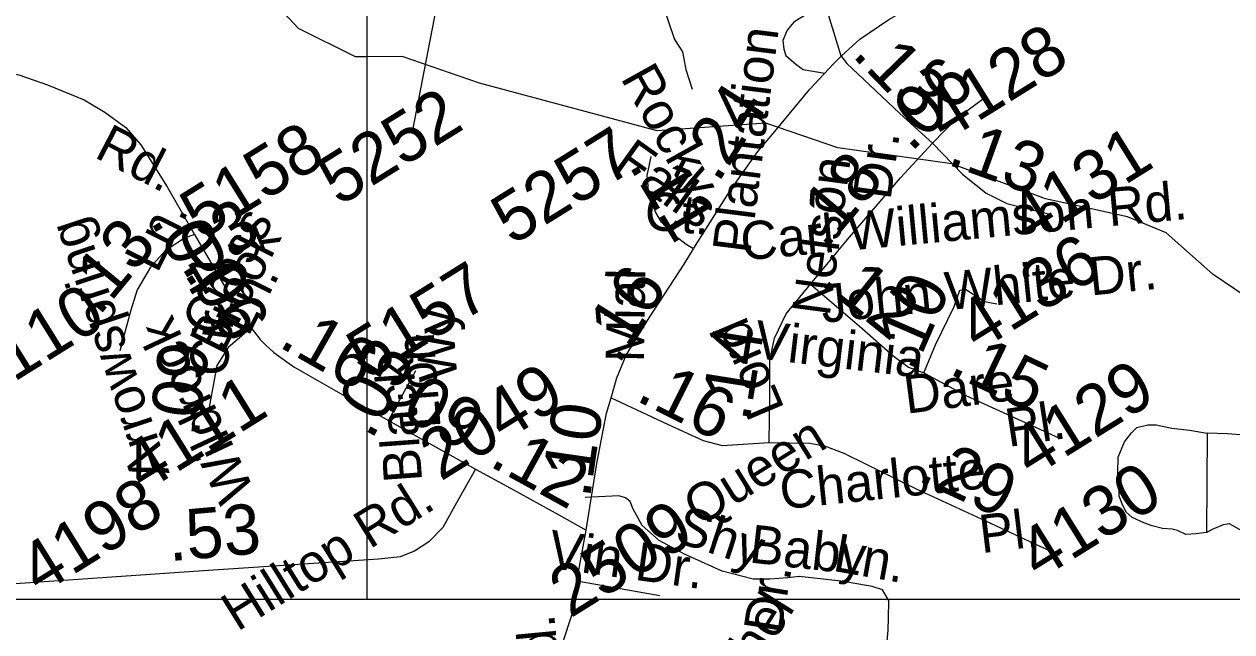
# Model space of a CAD drawing. Extents: x 2001466 to 31450019, y -30647475 to 847247.
# Drawn here: x 2156218 to 2162232, y 718722 to 721748 of the extents above; entities that cross this region are included whole.
import ezdxf

# ---------------------------------------------------------------- set-up
doc = ezdxf.new("R2010")
doc.units = 0
for name, color, linetype in [('Exist Hydrographic Misc Water Feature', 7, 'Continuous'), ('Exist Road Non-System Type 51', 7, 'Continuous'), ('Exist Road Non-System Type 51 Label', 7, 'Continuous'), ('Exist Road Secondary Mileage Hundredths English Label', 7, 'Continuous'), ('Exist Road Secondary Type 51 Attributed', 7, 'Continuous'), ('Exist Road Secondary Type 51 Label', 7, 'Continuous'), ('Exist Road Secondary Type 51 Number Label', 7, 'Continuous'), ('Map Preparation Inset Cut Line', 7, 'Continuous')]:
    doc.layers.add(name, color=color, linetype=linetype)

msp = doc.modelspace()

# ---------------------------------------------------------------- linework, layer by layer
at = {"layer": 'Exist Hydrographic Misc Water Feature'}
for points in [[(2157924.3, 721585.8), (2157868.1, 721585.3), (2157584.1, 721725.6), (2157215.2, 722123.5), (2157073.1, 722172.4), (2156940.2, 722188.2)], [(2161525.2, 720829.9), (2161304.1, 720878.7), (2160837, 721052.3), (2160270, 721132.8), (2159911, 721254.9), (2159370.1, 721216.8), (2158485.1, 721454.6), (2158101, 721587.1), (2157924.3, 721585.8)], [(2162725.1, 720105), (2162139.1, 720500.8), (2161905.1, 720709), (2161713, 720788.4), (2161525.2, 720829.9)]]:
    msp.add_lwpolyline(points, dxfattribs=at)
at = {"layer": 'Exist Road Non-System Type 51'}
msp.add_line((2162109.3, 719711.4), (2162106.1, 719217), dxfattribs=at)
for points in [[(2159560.9, 722264), (2159362.1, 722105.5), (2159338.5, 722055), (2159348.6, 721990.9), (2159399.2, 721842.6), (2159456.4, 721670.7), (2159496.9, 721610), (2159513.7, 721522.3), (2159544, 721424.6)], [(2160200.7, 721849.6), (2160124.9, 721805), (2160050.7, 721757.8), (2160017.1, 721717.3), (2159996.8, 721666.8), (2160000.2, 721622.9), (2160010.3, 721592.6), (2160060.9, 721548.8), (2160097.9, 721521.8), (2160135, 721515.1), (2160204.6, 721503.9)], [(2163386.2, 720643.3), (2163234.3, 720491.3), (2163166, 720438.2), (2163052.1, 720400.2), (2163082.5, 720286.3), (2163082.5, 720157.2), (2163097.7, 720066), (2163128.1, 719967.3), (2163097.7, 719914.1), (2163112.9, 719815.4), (2163074.9, 719739.4), (2162991, 719604.7), (2162897.3, 719617.7), (2162813.3, 719637), (2162690.6, 719659.7), (2162577.6, 719675.8), (2162383.8, 719695.2), (2162209.5, 719708.1), (2162109.3, 719711.4)], [(2161664.6, 719514.6), (2161665, 719592.6), (2161697.3, 719668.4), (2161732.8, 719713.6), (2161758.6, 719739.5), (2161813.5, 719752.4), (2161855.5, 719752.4), (2161933, 719736.3), (2162020.2, 719726.6), (2162109.3, 719711.4)], [(2162106.1, 719217), (2162054.4, 719210.5), (2162002.8, 719207.3), (2161960.8, 719226.6), (2161935, 719233.1), (2161886.5, 719236.3), (2161834.8, 719249.3), (2161792.9, 719265.4), (2161734.7, 719291.3), (2161705.7, 719317.1), (2161686.3, 719359.1), (2161670.2, 719397.9), (2161669.2, 719457), (2161664.6, 719514.6)], [(2159506.7, 719108.9), (2159379.4, 719176.8), (2159295.7, 719251.7), (2159275.5, 719287.5), (2159251.2, 719333.4), (2159235, 719371.3), (2159213, 719389.1), (2159179, 719398.8), (2159011.3, 719390.6)], [(2162106.1, 719217), (2162135.2, 719233.1), (2162190.1, 719255.7), (2162219.1, 719262.2), (2162280.5, 719226.6), (2162344.7, 719163.1), (2162389.1, 719108.7), (2162453.3, 719066.7), (2162527.4, 719024.7), (2162606.4, 718955.6), (2162655.8, 718925.9), (2162799, 718883.9), (2162806.7, 718882.9)], [(2160521.7, 718791.6), (2160524, 718878.7), (2160504.2, 718911.3), (2160492.9, 718931.3), (2160440.9, 718947), (2160298.6, 718972.3), (2160196.7, 718983.6), (2160076.6, 718997), (2160020.6, 718990.5), (2159930.7, 718984.2), (2159848.7, 718983.6), (2159694, 719024), (2159591.6, 719070.4), (2159506.7, 719108.9)], [(2159383.4, 718901.7), (2158969.7, 718974.8)], [(2160352.1, 717295), (2160335.8, 717341), (2160311.7, 717382.9), (2160305.6, 717396.8), (2160287.2, 717454.7), (2160260.9, 717518.5), (2160216, 717629.3), (2160232, 717786.3), (2160241.6, 717940.1), (2160254.4, 718023.4), (2160254.4, 718113.5), (2160273.6, 718206.4), (2160283.2, 718257.7), (2160324.9, 718344.2), (2160369.7, 718398.7), (2160417.7, 718469.2), (2160459.3, 718523.6), (2160492.9, 718575.4), (2160510.6, 718621.6), (2160520.1, 718730.9), (2160521.7, 718791.6)]]:
    msp.add_lwpolyline(points, dxfattribs=at)
at = {"layer": 'Exist Road Secondary Type 51 Attributed'}
msp.add_line((2158032.1, 719774.7), (2158169.4, 720023.5), dxfattribs=at)
for points in [[(2160286.7, 721589), (2160200, 721871.6), (2160116.7, 722114.8), (2160081.1, 722221.5), (2160073, 722250.6), (2160060, 722278.9), (2160018.3, 722343), (2159926.4, 722425.8), (2159796.7, 722486.6), (2159687.6, 722536.5), (2159644.2, 722560.3), (2159603.3, 722585.8), (2159562.9, 722613.1), (2159474.2, 722686.4), (2159320.4, 722834.3)], [(2160286.7, 721589), (2160378.8, 721672.8), (2160523.2, 721771.2), (2160682.2, 721861.3), (2160845.5, 721926.2), (2161054.8, 721984.9), (2161194.4, 721998.5), (2161587.9, 722021.5), (2162058.8, 722038.3), (2162481.5, 722042.4), (2163008.4, 722054), (2163418, 722057.1)], [(2159553.2, 720631.8), (2159731.6, 720915.7), (2159871.3, 721113.6), (2159956, 721214.2), (2160130.3, 721424.6), (2160248, 721550.3), (2160286.7, 721589)], [(2160286.7, 721589), (2160315, 721551.3), (2160369.9, 721501.1), (2160579.2, 721303.2), (2160740.8, 721155.5)], [(2155096.8, 721412.2), (2155256.7, 721457.1), (2155482.7, 721515.7), (2155639.7, 721538.8), (2155869.9, 721536.7), (2156018.5, 721528.3), (2156192.2, 721494.8), (2156334.5, 721446.6), (2156517.6, 721371.2), (2156620.2, 721310.5), (2156724.8, 721233), (2156800.1, 721147.1), (2156929.9, 720937.7), (2157067, 720701.1)], [(2160740.8, 721155.5), (2160859.1, 721275.9), (2161003.5, 721384.8)], [(2160134.5, 720454), (2160318.6, 720674.9), (2160581.8, 720982.8), (2160740.8, 721155.5)], [(2160740.8, 721155.5), (2160891, 721001.6), (2161009.2, 720906.3), (2161111.8, 720855), (2161326.3, 720802.6)], [(2159551.5, 720629), (2159515.3, 720650.4), (2159463.8, 720690.3), (2159429.2, 720719.7), (2159391.4, 720762.7), (2159363.1, 720810), (2159343.1, 720856.2), (2159327.4, 720905.6), (2159325.3, 720944.4), (2159320, 720995.9), (2159325.3, 721016.9), (2159341, 721089.4)], [(2157067, 720701.1), (2157016.7, 720682.2), (2156920.5, 720619.4), (2156847.2, 720537.7), (2156780.3, 720424.6), (2156748.9, 720324.1), (2156694.5, 720121)], [(2157067, 720701.1), (2157182.6, 720502)], [(2157182.6, 720502), (2157259.7, 720550.9), (2157290.8, 720571.7), (2157334.9, 720609.4)], [(2159141.4, 719886.4), (2159168.6, 719986.9), (2159215.7, 720100), (2159330.3, 720285.4), (2159504, 720553.4), (2159551.5, 720629)], [(2157182.6, 720502), (2157199.2, 720471.9), (2157255.4, 720375.2), (2157295.9, 720309.2), (2157311.8, 720283.3), (2157328, 720259.9), (2157347.9, 720235.4)], [(2159928.3, 719664.4), (2159931.5, 719899), (2159931.5, 720074.9), (2159954.5, 720183.8), (2160013.1, 720305.3), (2160134.5, 720454)], [(2160134.5, 720454), (2160388.7, 720234.1), (2160543.6, 720097.9), (2160621, 720039.3), (2160698.5, 720012.1)], [(2160698.5, 720012.1), (2160755.5, 720151.3), (2160848.6, 720341.9), (2160877.9, 720423.6), (2160906.2, 720428.8), (2161000.3, 720367), (2161061, 720354.5)], [(2157347.9, 720235.4), (2157234.4, 720137.7), (2157177.9, 720047.7), (2157140.2, 719840.3)], [(2157347.9, 720235.4), (2157393.3, 720178.4), (2157420.9, 720150.2), (2157461.8, 720113.5), (2157561.6, 720041.3), (2157805.4, 719902.4), (2158032.1, 719774.7)], [(2160698.5, 720012.1), (2160906.7, 719899), (2161370.2, 719687.5)], [(2159017.4, 719228.8), (2159070.3, 719559.7), (2159118.4, 719811), (2159141.4, 719886.4)], [(2159141.4, 719886.4), (2159421.9, 719756.6), (2159599.8, 719674.9), (2159693.9, 719649.8), (2159928.3, 719664.4)], [(2158032.1, 719774.7), (2158198.1, 719681.2), (2158466, 719532.5)], [(2159928.3, 719664.4), (2160130.3, 719662.3), (2160203.5, 719647.7), (2160299.8, 719612.1), (2160659.7, 719434), (2161004.5, 719274.9), (2161372.3, 719103.2)], [(2158466, 719532.5), (2158371.8, 719364.9), (2158302.8, 719241.4), (2158233.7, 719170.2), (2158162.5, 719124.1), (2158091.4, 719094.8), (2157982.6, 719084.3), (2157085.8, 719023.6), (2155980.8, 718948.2), (2155932.7, 718927.2)], [(2158466, 719532.5), (2158639.7, 719438.2), (2158880.4, 719304.2), (2159017.4, 719228.8)], [(2158901.3, 718669.6), (2158946.3, 718810), (2158971.4, 718983.8), (2159017.4, 719228.8)]]:
    msp.add_lwpolyline(points, dxfattribs=at)
at = {"layer": 'Exist Road Secondary Type 51 Number Label'}
msp.add_line((2158428.6, 722643.3), (2158151.5, 721219.7), dxfattribs=at)
at = {"layer": 'Map Preparation Inset Cut Line'}
for p, q in [((2157924.3, 723076.6), (2157924.3, 721585.8)), ((2157924.3, 721585.8), (2157924.3, 719948)), ((2157924.3, 719948), (2157924.3, 719162.1)), ((2157924.3, 719162.1), (2157924.3, 718882.9)), ((2157924.3, 718882.9), (2155172.5, 718882.9)), ((2159008.8, 718882.9), (2157924.3, 718882.9)), ((2159482.1, 718882.9), (2159008.8, 718882.9)), ((2160581.5, 718882.9), (2159482.1, 718882.9)), ((2162806.7, 718882.9), (2160581.5, 718882.9))]:
    msp.add_line(p, q, dxfattribs=at)

# ---------------------------------------------------------------- texts
at = {"layer": 'Exist Road Non-System Type 51 Label'}
for s, rotation, p in [('Shy', 341.90925, (2159449.7, 719174.2)), ('Vin Dr.', 352.06174, (2158820.2, 719042.2)), ('Baby', 353.61137, (2159824.1, 719068)), ('Ln.', 349.91636, (2160239.5, 719026.9)), ('Dr.', 80.96438, (2159987.4, 718707.3)), ('Weschel  ', 57.92852, (2159542.9, 718017.1))]:
    msp.add_text(s, height=190, rotation=rotation, dxfattribs=at).set_placement(p)
at = {"layer": 'Exist Road Secondary Mileage Hundredths English Label'}
for s, rotation, p in [('.13', 314.2215, (2160335.2, 721592.1)), ('.06', 44.98958, (2160634.2, 721105.2)), ('.24', 57.39176, (2159673.2, 720951.5)), ('.13', 340.16816, (2160808.5, 721051.1)), ('.18', 49.76898, (2160208, 720620.8)), ('.11', 300.95046, (2159226, 721045.4)), ('.03', 33.79919, (2157023.9, 720430.9)), ('.13', 50.59532, (2156590.6, 720289.2)), ('.04', 300.13822, (2156843.1, 720767.7)), ('.06', 301.50252, (2156997.7, 720540.3)), ('.16', 57.86425, (2159178.8, 720046.7)), ('.12', 321.3247, (2160178.3, 720454)), ('.10', 66.5301, (2160648.8, 720008.1)), ('.16', 330.33576, (2157478.2, 720145.4)), ('.05', 61.11339, (2157947.2, 719671.7)), ('.14', 80.94999, (2159829.6, 719763)), ('.09', 83.21976, (2157086, 719686.2)), ('.15', 334.5608, (2160816.7, 720009.9)), ('.16', 333.42176, (2159257.3, 719876.8)), ('.09', 330.60528, (2158006.1, 719842.9)), ('.10', 81.76087, (2159035.3, 719382.8)), ('.12', 331.16488, (2158527.5, 719551.5)), ('.29', 335.21238, (2160659.8, 719479)), ('.53', 5.09503, (2156941.5, 719073.5))]:
    msp.add_text(s, height=250, rotation=rotation, dxfattribs=at).set_placement(p)
at = {"layer": 'Exist Road Secondary Type 51 Label'}
for s, rotation, p in [('Plantation', 82.7818, (2159833.8, 720600.7)), ('Rocky', 299.1668, (2159185.8, 721480.4)), ('Rd.', 332.65086, (2156562.1, 721087.9)), ('Falls', 324.40941, (2159146.4, 721032.9)), ('Dr.', 82.09614, (2160532, 720868.5)), ('Nelson', 82.37386, (2160228.9, 720289.7)), ('Carl Williamson Rd.', 5.34029, (2159794.5, 720570.6)), ('Ct.', 354.83795, (2159301.8, 720727.7)), ('Arrowspring', 108.39326, (2156943.2, 719512.8)), ('Ln.', 63.36229, (2156881.2, 720503)), ('Cross', 63.36229, (2157165.2, 720177.2)), ('Brook', 63.36229, (2157204.7, 720093.6)), ('John White Dr.', 5.83014, (2160195, 720260)), ('Ln.', 63.36229, (2157334.3, 720188)), ('Mial', 88.99577, (2159303.8, 720063.3)), ('Cir.', 82.23824, (2157223, 719985.9)), ('Wildrock', 115.1378, (2157368.1, 719422.9)), ('Wy', 94.19252, (2158376.1, 719976.8)), ('Lord', 112.86802, (2160006.2, 719832.5)), ('Virginia', 353.24274, (2159846.8, 720085.8)), ('Lion', 94.19252, (2158292.3, 719737.1)), ('Black', 94.19252, (2158200.4, 719472.2)), ('Dare', 7.33896, (2160611.7, 719807.5)), ('Pl.', 8.77099, (2161119.7, 719642)), ('Queen', 31.91803, (2159580, 719241.9)), ('Charlotte', 5.94638, (2159990.2, 719331.3)), ('Hilltop Rd.', 31.91803, (2157280, 718721.1)), ('Pl.', 6.9317, (2160985.6, 719113.3)), ('Rd.', 95.40838, (2158894.4, 718420.5))]:
    msp.add_text(s, height=190, rotation=rotation, dxfattribs=at).set_placement(p)
at = {"layer": 'Exist Road Secondary Type 51 Number Label'}
for s, p in [('4128', (2160804, 721159.3)), ('5252', (2157786.8, 720838)), ('5158', (2157100.3, 720669.9)), ('5257', (2158648.8, 720643.4)), ('4131', (2161223.2, 720648.6)), ('4136', (2160968.9, 720113.5)), ('5157', (2157929.6, 719972)), ('4110', (2156008, 719864.6)), ('4129', (2161234.6, 719485.4)), ('2049', (2158292.2, 719469)), ('4111', (2156814, 719411.8)), ('4130', (2161270.9, 718976.3)), ('4198', (2156297.4, 718902.1)), ('2509', (2158937.9, 718787.7))]:
    msp.add_text(s, height=250, rotation=31.91803, dxfattribs=at).set_placement(p)

doc.saveas('drawing.dxf')
